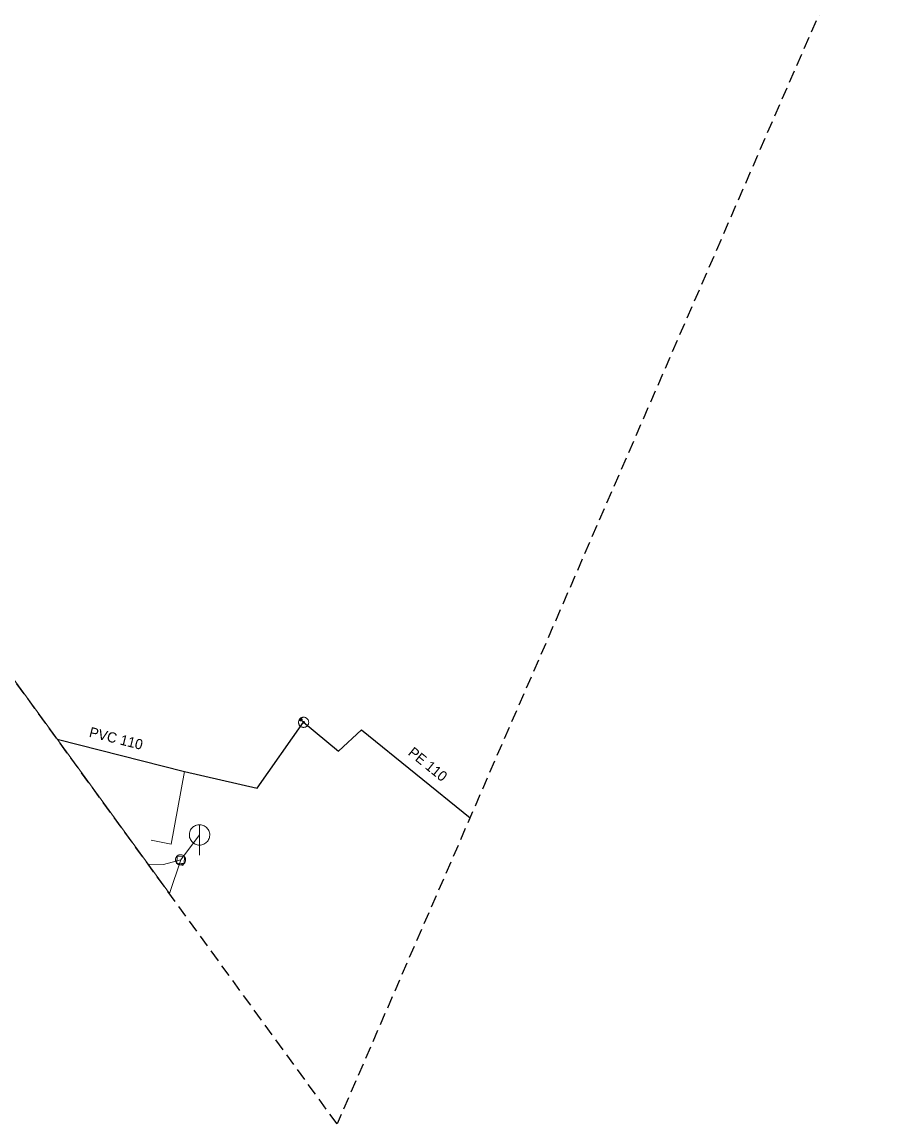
# Model space of a CAD drawing. Extents: x -724358 to -723714, y -973310 to -972026.
# Drawn here: x -724272.1 to -724185.8, y -973309.6 to -973201.5 of the extents above; entities that cross this region are included whole.
import ezdxf

# ---------------------------------------------------------------- set-up
doc = ezdxf.new("R2010")
doc.units = 0
doc.header["$LTSCALE"] = 0.4
doc.header["$PDMODE"] = 32
doc.header["$PDSIZE"] = 0.2
doc.linetypes.add('MEDIUM_DASHED', pattern=[4.5, 3, -1.5])
for name, color, linetype, lineweight in [('1', 7, 'Continuous', 13), ('11', 7, 'Continuous', 13), ('13', 7, 'Continuous', 13), ('14', 7, 'Continuous', 13), ('17', 7, 'Continuous', 25), ('22', 7, 'Continuous', 13), ('4', 7, 'Continuous', 13), ('47', 7, 'Continuous', 13), ('9', 7, 'Continuous', 13)]:
    doc.layers.add(name, color=color, linetype=linetype, lineweight=lineweight)

msp = doc.modelspace()

# ---------------------------------------------------------------- linework, layer by layer
at = {"layer": '1', "linetype": 'MEDIUM_DASHED', "lineweight": 25}
msp.add_lwpolyline([(-723809.944, -972026.35), (-723713.647, -972034.723), (-723734.581, -972361.295), (-724123.956, -973039.561), (-724241.187, -973309.611), (-724358.418, -973148.418), (-723860.186, -972315.24)], close=True, dxfattribs=at)
at = {"layer": '11'}
msp.add_line((-724254.68, -973281.25), (-724256.51, -973283.709), dxfattribs=at)
for points in [[(-724256.51, -973283.709), (-724257.639, -973286.989), (-724289.277, -973243.486), (-724282.809, -973218.84), (-724286.02, -973211.489), (-724288.62, -973206.05), (-724287.949, -973204.649), (-724287.69, -973202.64), (-724312.92, -973168.17), (-724315.44, -973166.19), (-724319.85, -973166.51), (-724322.98, -973169.03), (-724328.449, -973164.989)], [(-724259.739, -973284.101), (-724259.699, -973284.109), (-724258.23, -973284.14), (-724256.51, -973283.709)]]:
    msp.add_lwpolyline(points, dxfattribs=at)
at = {"layer": '13'}
msp.add_lwpolyline([(-724256.149, -973275.027), (-724257.473, -973282.151), (-724259.427, -973281.772)], dxfattribs=at)
at = {"layer": '14'}
msp.add_line((-724244.467, -973270.199), (-724244.749, -973269.932), dxfattribs=at)
at = {"layer": '17'}
for points in [[(-724268.646, -973271.854), (-724256.149, -973275.026), (-724249.013, -973276.664), (-724244.467, -973270.199)], [(-724244.467, -973270.199), (-724241.034, -973273.035), (-724238.802, -973270.953), (-724228.144, -973279.566)]]:
    msp.add_lwpolyline(points, dxfattribs=at)
at = {"layer": '22'}
msp.add_line((-724254.68, -973283.25), (-724254.679, -973280.25), dxfattribs=at)
msp.add_lwpolyline([(-724253.68, -973281.25), (-724253.685, -973281.141), (-724253.703, -973281.033), (-724253.733, -973280.927), (-724253.773, -973280.826), (-724253.825, -973280.729), (-724253.887, -973280.639), (-724253.959, -973280.556), (-724254.039, -973280.482), (-724254.127, -973280.416), (-724254.221, -973280.361), (-724254.321, -973280.316), (-724254.426, -973280.283), (-724254.533, -973280.261), (-724254.642, -973280.251), (-724254.752, -973280.253), (-724254.86, -973280.267), (-724254.967, -973280.292), (-724255.07, -973280.329), (-724255.168, -973280.378), (-724255.26, -973280.436), (-724255.346, -973280.505), (-724255.423, -973280.582), (-724255.492, -973280.668), (-724255.551, -973280.76), (-724255.599, -973280.858), (-724255.636, -973280.961), (-724255.662, -973281.068), (-724255.676, -973281.176), (-724255.679, -973281.286), (-724255.669, -973281.395), (-724255.648, -973281.502), (-724255.614, -973281.606), (-724255.57, -973281.706), (-724255.515, -973281.801), (-724255.449, -973281.889), (-724255.375, -973281.969), (-724255.292, -973282.041), (-724255.202, -973282.103), (-724255.106, -973282.155), (-724255.004, -973282.196), (-724254.899, -973282.226), (-724254.791, -973282.244), (-724254.681, -973282.25), (-724254.572, -973282.244), (-724254.464, -973282.226), (-724254.359, -973282.197), (-724254.257, -973282.156), (-724254.16, -973282.104), (-724254.07, -973282.042), (-724253.987, -973281.971), (-724253.912, -973281.891), (-724253.847, -973281.803), (-724253.791, -973281.709), (-724253.747, -973281.609), (-724253.713, -973281.505), (-724253.691, -973281.397), (-724253.681, -973281.288)], close=True, dxfattribs=at)
at = {"layer": '4'}
for points in [[(-724256.041, -973283.729), (-724256.04, -973283.677), (-724256.046, -973283.623), (-724256.056, -973283.573), (-724256.071, -973283.523), (-724256.092, -973283.475), (-724256.12, -973283.429), (-724256.149, -973283.387), (-724256.185, -973283.348), (-724256.222, -973283.312), (-724256.264, -973283.28), (-724256.31, -973283.253), (-724256.357, -973283.233), (-724256.406, -973283.215), (-724256.458, -973283.204), (-724256.509, -973283.2), (-724256.561, -973283.199), (-724256.615, -973283.205), (-724256.666, -973283.214), (-724256.715, -973283.229), (-724256.763, -973283.252), (-724256.809, -973283.278), (-724256.851, -973283.307), (-724256.891, -973283.343), (-724256.926, -973283.38), (-724256.957, -973283.422), (-724256.984, -973283.468), (-724257.006, -973283.515), (-724257.023, -973283.564), (-724257.032, -973283.617), (-724257.038, -973283.667), (-724257.038, -973283.719), (-724257.033, -973283.773), (-724257.025, -973283.824), (-724257.008, -973283.874), (-724256.987, -973283.921), (-724256.961, -973283.968), (-724256.931, -973284.01), (-724256.896, -973284.049), (-724256.857, -973284.084), (-724256.816, -973284.116), (-724256.77, -973284.142), (-724256.723, -973284.164), (-724256.673, -973284.181), (-724256.621, -973284.191), (-724256.571, -973284.197), (-724256.519, -973284.197), (-724256.465, -973284.192), (-724256.415, -973284.183), (-724256.364, -973284.166), (-724256.316, -973284.145), (-724256.27, -973284.12), (-724256.228, -973284.09), (-724256.19, -973284.054), (-724256.154, -973284.017), (-724256.122, -973283.974), (-724256.095, -973283.928), (-724256.074, -973283.882), (-724256.057, -973283.832), (-724256.046, -973283.78)], [(-724256.868, -973283.327), (-724256.161, -973283.37), (-724256.203, -973284.063), (-724256.91, -973284.019)]]:
    msp.add_lwpolyline(points, close=True, dxfattribs=at)
msp.add_point((-724256.343, -973284.159), dxfattribs=at)
at = {"layer": '47'}
for points in [[(-724244.081, -973270.517), (-724244.05, -973270.475), (-724244.023, -973270.43), (-724244.002, -973270.382), (-724243.985, -973270.333), (-724243.973, -973270.281), (-724243.968, -973270.229), (-724243.968, -973270.177), (-724243.973, -973270.125), (-724243.983, -973270.074), (-724243.998, -973270.024), (-724244.019, -973269.975), (-724244.045, -973269.93), (-724244.075, -973269.888), (-724244.11, -973269.848), (-724244.148, -973269.813), (-724244.19, -973269.782), (-724244.235, -973269.755), (-724244.284, -973269.734), (-724244.332, -973269.717), (-724244.384, -973269.705), (-724244.436, -973269.7), (-724244.489, -973269.699), (-724244.541, -973269.704), (-724244.592, -973269.714), (-724244.641, -973269.73), (-724244.69, -973269.751), (-724244.735, -973269.777), (-724244.777, -973269.807), (-724244.817, -973269.842), (-724244.852, -973269.88), (-724244.883, -973269.922), (-724244.91, -973269.967), (-724244.932, -973270.015), (-724244.948, -973270.064), (-724244.96, -973270.116), (-724244.966, -973270.167), (-724244.967, -973270.22), (-724244.962, -973270.272), (-724244.951, -973270.324), (-724244.935, -973270.373), (-724244.914, -973270.422), (-724244.889, -973270.467), (-724244.858, -973270.509), (-724244.823, -973270.549), (-724244.785, -973270.584), (-724244.743, -973270.615), (-724244.698, -973270.642), (-724244.651, -973270.664), (-724244.601, -973270.68), (-724244.549, -973270.692), (-724244.498, -973270.698), (-724244.446, -973270.698), (-724244.394, -973270.693), (-724244.342, -973270.682), (-724244.292, -973270.667), (-724244.243, -973270.646), (-724244.199, -973270.62), (-724244.156, -973270.59), (-724244.116, -973270.555)], [(-724244.403, -973270.251), (-724244.398, -973270.244), (-724244.394, -973270.236), (-724244.39, -973270.229), (-724244.388, -973270.221), (-724244.386, -973270.212), (-724244.385, -973270.204), (-724244.384, -973270.195), (-724244.385, -973270.186), (-724244.387, -973270.178), (-724244.39, -973270.17), (-724244.393, -973270.162), (-724244.398, -973270.154), (-724244.402, -973270.148), (-724244.407, -973270.141), (-724244.414, -973270.135), (-724244.421, -973270.13), (-724244.429, -973270.126), (-724244.436, -973270.122), (-724244.444, -973270.12), (-724244.453, -973270.118), (-724244.461, -973270.117), (-724244.47, -973270.116), (-724244.479, -973270.117), (-724244.488, -973270.119), (-724244.495, -973270.122), (-724244.503, -973270.125), (-724244.511, -973270.13), (-724244.517, -973270.134), (-724244.524, -973270.139), (-724244.53, -973270.146), (-724244.535, -973270.153), (-724244.539, -973270.161), (-724244.543, -973270.168), (-724244.545, -973270.176), (-724244.547, -973270.185), (-724244.549, -973270.193), (-724244.549, -973270.202), (-724244.548, -973270.211), (-724244.546, -973270.22), (-724244.543, -973270.227), (-724244.54, -973270.235), (-724244.535, -973270.243), (-724244.531, -973270.249), (-724244.526, -973270.256), (-724244.519, -973270.262), (-724244.512, -973270.267), (-724244.504, -973270.271), (-724244.497, -973270.275), (-724244.489, -973270.277), (-724244.48, -973270.279), (-724244.472, -973270.281), (-724244.463, -973270.281), (-724244.454, -973270.28), (-724244.446, -973270.278), (-724244.438, -973270.275), (-724244.43, -973270.272), (-724244.422, -973270.267), (-724244.416, -973270.263), (-724244.409, -973270.258)]]:
    msp.add_lwpolyline(points, close=True, dxfattribs=at)
at = {"layer": '9'}
for points in [[(-724244.875, -973269.932), (-724244.875, -973269.945), (-724244.872, -973269.958), (-724244.87, -973269.971), (-724244.865, -973269.983), (-724244.858, -973269.995), (-724244.852, -973270.006), (-724244.843, -973270.016), (-724244.833, -973270.026), (-724244.823, -973270.034), (-724244.813, -973270.041), (-724244.801, -973270.047), (-724244.789, -973270.052), (-724244.776, -973270.055), (-724244.762, -973270.057), (-724244.75, -973270.059), (-724244.737, -973270.058), (-724244.723, -973270.056), (-724244.711, -973270.053), (-724244.698, -973270.048), (-724244.686, -973270.042), (-724244.676, -973270.035), (-724244.666, -973270.027), (-724244.656, -973270.017), (-724244.647, -973270.007), (-724244.641, -973269.996), (-724244.635, -973269.984), (-724244.63, -973269.972), (-724244.627, -973269.959), (-724244.625, -973269.946), (-724244.622, -973269.933), (-724244.624, -973269.92), (-724244.625, -973269.907), (-724244.629, -973269.894), (-724244.634, -973269.882), (-724244.639, -973269.87), (-724244.647, -973269.859), (-724244.654, -973269.849), (-724244.664, -973269.839), (-724244.674, -973269.831), (-724244.686, -973269.824), (-724244.698, -973269.818), (-724244.71, -973269.813), (-724244.723, -973269.81), (-724244.735, -973269.808), (-724244.749, -973269.807), (-724244.762, -973269.807), (-724244.774, -973269.809), (-724244.788, -973269.812), (-724244.799, -973269.817), (-724244.811, -973269.823), (-724244.823, -973269.83), (-724244.833, -973269.838), (-724244.843, -973269.848), (-724244.85, -973269.858), (-724244.858, -973269.869), (-724244.864, -973269.881), (-724244.869, -973269.893), (-724244.872, -973269.906), (-724244.874, -973269.919)], [(-724244.855, -973269.932), (-724244.855, -973269.943), (-724244.853, -973269.954), (-724244.85, -973269.965), (-724244.847, -973269.975), (-724244.842, -973269.985), (-724244.836, -973269.994), (-724244.828, -973270.003), (-724244.821, -973270.011), (-724244.811, -973270.018), (-724244.803, -973270.024), (-724244.793, -973270.029), (-724244.782, -973270.033), (-724244.772, -973270.036), (-724244.761, -973270.039), (-724244.75, -973270.039), (-724244.739, -973270.039), (-724244.728, -973270.037), (-724244.717, -973270.034), (-724244.706, -973270.03), (-724244.696, -973270.025), (-724244.688, -973270.019), (-724244.679, -973270.012), (-724244.671, -973270.004), (-724244.664, -973269.995), (-724244.657, -973269.986), (-724244.652, -973269.976), (-724244.649, -973269.966), (-724244.646, -973269.955), (-724244.644, -973269.944), (-724244.642, -973269.933), (-724244.642, -973269.922), (-724244.644, -973269.911), (-724244.647, -973269.9), (-724244.652, -973269.89), (-724244.657, -973269.88), (-724244.663, -973269.871), (-724244.669, -973269.862), (-724244.678, -973269.854), (-724244.686, -973269.847), (-724244.696, -973269.841), (-724244.706, -973269.836), (-724244.715, -973269.832), (-724244.727, -973269.829), (-724244.737, -973269.827), (-724244.749, -973269.827), (-724244.76, -973269.826), (-724244.771, -973269.828), (-724244.782, -973269.831), (-724244.791, -973269.835), (-724244.801, -973269.84), (-724244.811, -973269.846), (-724244.82, -973269.853), (-724244.828, -973269.861), (-724244.835, -973269.87), (-724244.84, -973269.879), (-724244.845, -973269.889), (-724244.85, -973269.899), (-724244.853, -973269.91), (-724244.855, -973269.921)], [(-724244.836, -973269.932), (-724244.836, -973269.941), (-724244.835, -973269.95), (-724244.831, -973269.959), (-724244.828, -973269.967), (-724244.825, -973269.975), (-724244.82, -973269.983), (-724244.813, -973269.99), (-724244.808, -973269.996), (-724244.801, -973270.002), (-724244.793, -973270.007), (-724244.784, -973270.011), (-724244.777, -973270.014), (-724244.767, -973270.017), (-724244.759, -973270.018), (-724244.75, -973270.02), (-724244.74, -973270.019), (-724244.732, -973270.018), (-724244.723, -973270.015), (-724244.715, -973270.012), (-724244.706, -973270.008), (-724244.698, -973270.003), (-724244.691, -973269.997), (-724244.686, -973269.991), (-724244.679, -973269.984), (-724244.674, -973269.976), (-724244.671, -973269.968), (-724244.668, -973269.96), (-724244.664, -973269.951), (-724244.664, -973269.942), (-724244.661, -973269.933), (-724244.663, -973269.924), (-724244.664, -973269.915), (-724244.666, -973269.906), (-724244.669, -973269.898), (-724244.674, -973269.89), (-724244.679, -973269.882), (-724244.684, -973269.875), (-724244.691, -973269.869), (-724244.698, -973269.863), (-724244.706, -973269.858), (-724244.713, -973269.854), (-724244.722, -973269.851), (-724244.73, -973269.848), (-724244.74, -973269.847), (-724244.749, -973269.846), (-724244.757, -973269.846), (-724244.767, -973269.847), (-724244.776, -973269.85), (-724244.784, -973269.853), (-724244.791, -973269.857), (-724244.799, -973269.862), (-724244.806, -973269.868), (-724244.813, -973269.874), (-724244.818, -973269.881), (-724244.823, -973269.889), (-724244.828, -973269.897), (-724244.831, -973269.905), (-724244.833, -973269.914), (-724244.835, -973269.923)], [(-724244.816, -973269.932), (-724244.816, -973269.939), (-724244.815, -973269.946), (-724244.813, -973269.953), (-724244.811, -973269.959), (-724244.808, -973269.965), (-724244.804, -973269.971), (-724244.799, -973269.977), (-724244.794, -973269.982), (-724244.789, -973269.986), (-724244.782, -973269.99), (-724244.777, -973269.993), (-724244.771, -973269.996), (-724244.764, -973269.997), (-724244.757, -973270), (-724244.75, -973270), (-724244.742, -973270), (-724244.735, -973269.998), (-724244.728, -973269.997), (-724244.723, -973269.994), (-724244.715, -973269.991), (-724244.711, -973269.987), (-724244.705, -973269.983), (-724244.7, -973269.978), (-724244.696, -973269.972), (-724244.691, -973269.966), (-724244.688, -973269.96), (-724244.686, -973269.954), (-724244.684, -973269.947), (-724244.683, -973269.94), (-724244.681, -973269.933), (-724244.681, -973269.926), (-724244.683, -973269.919), (-724244.684, -973269.912), (-724244.688, -973269.906), (-724244.691, -973269.899), (-724244.695, -973269.894), (-724244.698, -973269.888), (-724244.703, -973269.883), (-724244.71, -973269.879), (-724244.715, -973269.875), (-724244.722, -973269.872), (-724244.728, -973269.869), (-724244.735, -973269.867), (-724244.742, -973269.866), (-724244.749, -973269.866), (-724244.755, -973269.866), (-724244.762, -973269.866), (-724244.769, -973269.868), (-724244.776, -973269.871), (-724244.782, -973269.874), (-724244.788, -973269.878), (-724244.794, -973269.882), (-724244.799, -973269.887), (-724244.803, -973269.893), (-724244.806, -973269.898), (-724244.809, -973269.905), (-724244.813, -973269.911), (-724244.813, -973269.918), (-724244.816, -973269.925)], [(-724244.796, -973269.932), (-724244.796, -973269.937), (-724244.796, -973269.942), (-724244.794, -973269.947), (-724244.793, -973269.951), (-724244.791, -973269.956), (-724244.788, -973269.96), (-724244.784, -973269.963), (-724244.781, -973269.967), (-724244.777, -973269.97), (-724244.774, -973269.973), (-724244.769, -973269.975), (-724244.764, -973269.977), (-724244.76, -973269.978), (-724244.755, -973269.98), (-724244.75, -973269.98), (-724244.745, -973269.98), (-724244.74, -973269.979), (-724244.735, -973269.978), (-724244.73, -973269.976), (-724244.725, -973269.974), (-724244.722, -973269.971), (-724244.718, -973269.968), (-724244.715, -973269.964), (-724244.712, -973269.961), (-724244.708, -973269.957), (-724244.706, -973269.952), (-724244.705, -973269.948), (-724244.703, -973269.943), (-724244.703, -973269.938), (-724244.701, -973269.933), (-724244.701, -973269.928), (-724244.703, -973269.923), (-724244.703, -973269.918), (-724244.706, -973269.914), (-724244.708, -973269.909), (-724244.711, -973269.905), (-724244.713, -973269.901), (-724244.717, -973269.898), (-724244.72, -973269.895), (-724244.725, -973269.892), (-724244.73, -973269.89), (-724244.733, -973269.888), (-724244.739, -973269.887), (-724244.744, -973269.886), (-724244.749, -973269.886), (-724244.754, -973269.886), (-724244.759, -973269.887), (-724244.764, -973269.887), (-724244.767, -973269.889), (-724244.772, -973269.891), (-724244.777, -973269.894), (-724244.779, -973269.897), (-724244.784, -973269.9), (-724244.786, -973269.904), (-724244.789, -973269.908), (-724244.791, -973269.913), (-724244.794, -973269.917), (-724244.794, -973269.922), (-724244.796, -973269.927)], [(-724244.776, -973269.932), (-724244.776, -973269.935), (-724244.777, -973269.938), (-724244.776, -973269.94), (-724244.774, -973269.943), (-724244.774, -973269.946), (-724244.772, -973269.948), (-724244.769, -973269.95), (-724244.767, -973269.952), (-724244.766, -973269.954), (-724244.764, -973269.956), (-724244.761, -973269.958), (-724244.757, -973269.959), (-724244.755, -973269.959), (-724244.752, -973269.96), (-724244.75, -973269.96), (-724244.747, -973269.96), (-724244.744, -973269.96), (-724244.74, -973269.959), (-724244.739, -973269.958), (-724244.735, -973269.957), (-724244.733, -973269.955), (-724244.73, -973269.953), (-724244.728, -973269.951), (-724244.728, -973269.949), (-724244.725, -973269.947), (-724244.725, -973269.944), (-724244.723, -973269.941), (-724244.723, -973269.939), (-724244.722, -973269.936), (-724244.72, -973269.933), (-724244.722, -973269.93), (-724244.722, -973269.927), (-724244.723, -973269.924), (-724244.723, -973269.922), (-724244.725, -973269.919), (-724244.727, -973269.917), (-724244.728, -973269.914), (-724244.73, -973269.912), (-724244.733, -973269.911), (-724244.735, -973269.909), (-724244.737, -973269.908), (-724244.74, -973269.907), (-724244.742, -973269.906), (-724244.745, -973269.906), (-724244.749, -973269.905), (-724244.752, -973269.906), (-724244.755, -973269.905), (-724244.757, -973269.907), (-724244.76, -973269.907), (-724244.762, -973269.908), (-724244.764, -973269.91), (-724244.767, -973269.911), (-724244.769, -973269.913), (-724244.771, -973269.916), (-724244.772, -973269.918), (-724244.774, -973269.921), (-724244.774, -973269.923), (-724244.776, -973269.926), (-724244.776, -973269.929)], [(-724244.757, -973269.932), (-724244.757, -973269.934), (-724244.757, -973269.934), (-724244.755, -973269.934), (-724244.755, -973269.936), (-724244.757, -973269.937), (-724244.755, -973269.937), (-724244.755, -973269.937), (-724244.755, -973269.939), (-724244.755, -973269.939), (-724244.754, -973269.94), (-724244.752, -973269.94), (-724244.752, -973269.94), (-724244.752, -973269.941), (-724244.75, -973269.941), (-724244.75, -973269.941), (-724244.749, -973269.941), (-724244.747, -973269.941), (-724244.747, -973269.94), (-724244.747, -973269.94), (-724244.745, -973269.94), (-724244.745, -973269.939), (-724244.745, -973269.939), (-724244.744, -973269.938), (-724244.744, -973269.938), (-724244.742, -973269.937), (-724244.742, -973269.936), (-724244.74, -973269.935), (-724244.74, -973269.935), (-724244.74, -973269.934), (-724244.74, -973269.933), (-724244.74, -973269.932), (-724244.74, -973269.931), (-724244.74, -973269.931), (-724244.742, -973269.93), (-724244.742, -973269.929), (-724244.742, -973269.928), (-724244.742, -973269.928), (-724244.744, -973269.927), (-724244.744, -973269.927), (-724244.745, -973269.926), (-724244.745, -973269.926), (-724244.747, -973269.925), (-724244.747, -973269.925), (-724244.747, -973269.925), (-724244.749, -973269.925), (-724244.75, -973269.925), (-724244.75, -973269.925), (-724244.75, -973269.925), (-724244.752, -973269.926), (-724244.752, -973269.925), (-724244.754, -973269.927), (-724244.754, -973269.927), (-724244.755, -973269.927), (-724244.755, -973269.927), (-724244.755, -973269.929), (-724244.755, -973269.93), (-724244.755, -973269.931), (-724244.757, -973269.931), (-724244.757, -973269.932)]]:
    msp.add_lwpolyline(points, close=True, dxfattribs=at)

# ---------------------------------------------------------------- texts
at = {"layer": '1'}
for s, rotation, p in [('PVC 110 ', 346, (-724265.582, -973271.615)), ('PE 110', 321, (-724234.299, -973273.324))]:
    msp.add_text(s, height=1, rotation=rotation, dxfattribs=at).set_placement(p)

doc.saveas('drawing.dxf')
